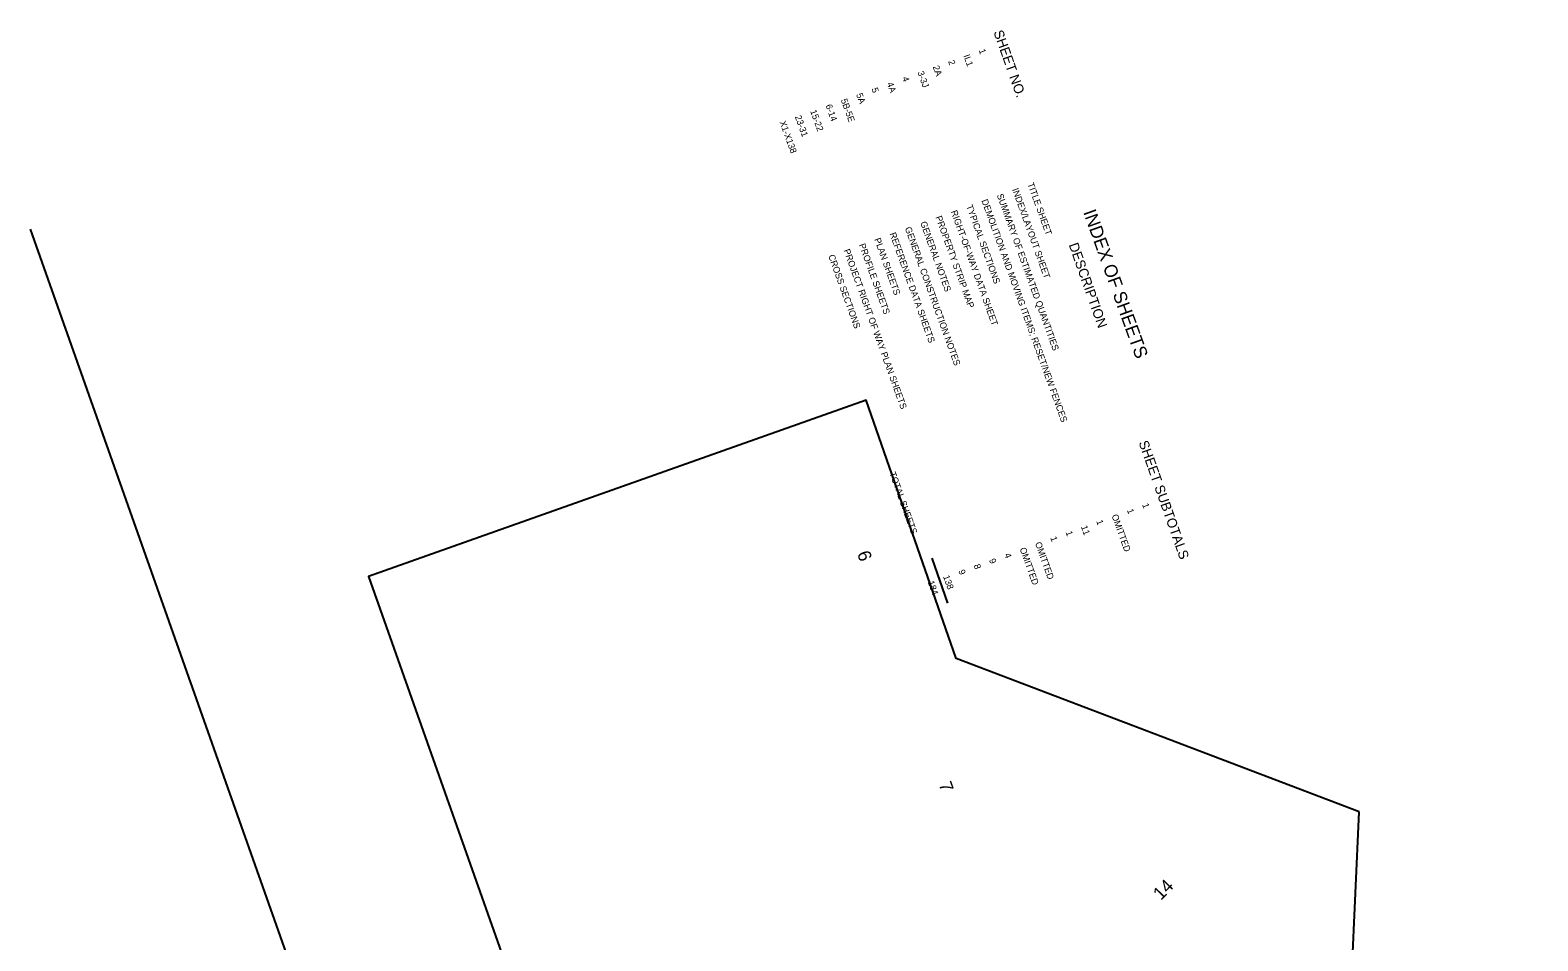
# Model space of a CAD drawing. Extents: x 2000223 to 2009769, y 1132098 to 1143273.
# Drawn here: x 2000223 to 2009479, y 1137686 to 1143273 of the extents above; entities that cross this region are included whole.
import ezdxf

# ---------------------------------------------------------------- set-up
doc = ezdxf.new("R2010")
doc.units = 0
doc.layers.add('RD_SHT_ShtClip', color=7, linetype='Continuous')
doc.layers.add('RD_SHT_TX', color=7, linetype='Continuous')

msp = doc.modelspace()

# ---------------------------------------------------------------- linework, layer by layer
at = {"layer": 'RD_SHT_ShtClip'}
msp.add_lwpolyline([(2008381.9, 1138477.9), (2005909, 1139418.3), (2005354.6, 1141003.5), (2002299.7, 1139921.3), (2004881.5, 1132623.3), (2009479.3, 1134249.9), (2008336.7, 1137479.8)], close=True, dxfattribs=at)
at = {"layer": 'RD_SHT_TX'}
for p, q in [((2000223, 1142053.2), (2003744.9, 1132097.8)), ((2005758, 1140032.7), (2005855.7, 1139756.7))]:
    msp.add_line(p, q, dxfattribs=at)

# ---------------------------------------------------------------- texts
for s, height, rotation, p in [('SHEET NO.', 60, 289.48201, (2006136.7, 1143261.6)), ('1', 40, 289.84288, (2006046, 1143150.3)), ('2', 40, 289.84288, (2005857.9, 1143082.4)), ('IL1', 40, 289.84288, (2005951.9, 1143116.3)), ('4', 40, 289.84288, (2005575.7, 1142980.5)), ('3-3J', 40, 289.84288, (2005669.7, 1143014.5)), ('2A', 40, 289.84288, (2005763.8, 1143048.4)), ('5A', 40, 289.84288, (2005293.5, 1142878.7)), ('5', 40, 289.84288, (2005387.5, 1142912.6)), ('4A', 40, 289.84288, (2005481.6, 1142946.6)), ('15-22', 40, 289.84288, (2005011.3, 1142776.9)), ('6-14', 40, 289.84288, (2005105.4, 1142810.8)), ('5B-5E', 40, 289.84288, (2005199.4, 1142844.8)), ('X1-X138', 40, 289.84288, (2004823.2, 1142709)), ('23-31', 40, 289.84288, (2004917.2, 1142742.9)), ('TITLE SHEET', 40, 289.84288, (2006345.1, 1142329.7)), ('DEMOLITION AND MOVING ITEMS; RESET/NEW FENCES', 40, 289.84288, (2006062.9, 1142227.8)), ('SUMMARY OF ESTIMATED QUANTITIES', 40, 289.84288, (2006157, 1142261.8)), ('INDEX/LAYOUT SHEET', 40, 289.84288, (2006251, 1142295.7)), ('PROPERTY STRIP MAP', 40, 289.84288, (2005780.7, 1142126)), ('RIGHT-OF-WAY DATA SHEET', 40, 289.84288, (2005874.8, 1142160)), ('TYPICAL SECTIONS', 40, 289.84288, (2005968.8, 1142193.9)), ('INDEX OF SHEETS', 80, 289.84288, (2006686.8, 1142156.7)), ('GENERAL CONSTRUCTION NOTES', 40, 289.84288, (2005592.6, 1142058.1)), ('GENERAL NOTES', 40, 289.84288, (2005686.6, 1142092.1)), ('PROFILE SHEETS', 40, 289.84288, (2005310.4, 1141956.3)), ('PLAN SHEETS', 40, 289.84288, (2005404.5, 1141990.2)), ('REFERENCE DATA SHEETS', 40, 289.84288, (2005498.5, 1142024.2)), ('DESCRIPTION', 60, 289.48201, (2006598.4, 1141956.5)), ('CROSS SECTIONS', 40, 289.84288, (2005122.3, 1141888.4)), ('PROJECT RIGHT OF WAY PLAN SHEETS', 40, 289.84288, (2005216.3, 1141922.4)), ('SHEET SUBTOTALS', 60, 289.48201, (2007027.6, 1140743.3)), ('                                                                                             TOTAL SHEETS', 40, 289.84288, (2005028.2, 1141854.5)), ('OMITTED', 40, 289.84288, (2006861.6, 1140294.6)), ('1', 40, 289.84288, (2006955.7, 1140328.6)), ('1', 40, 289.84288, (2007049.7, 1140362.5)), ('1', 40, 289.84288, (2006579.4, 1140192.8)), ('11', 40, 289.84288, (2006673.5, 1140226.7)), ('1', 40, 289.84288, (2006767.6, 1140260.7)), ('OMITTED', 40, 289.84288, (2006297.2, 1140091)), ('OMITTED', 40, 289.84288, (2006391.3, 1140124.9)), ('1', 40, 289.84288, (2006485.4, 1140158.9)), ('6', 80, 289.48201, (2005298.8, 1140062.8)), ('9', 40, 289.84288, (2006109.1, 1140023.1)), ('4', 40, 289.84288, (2006203.2, 1140057)), ('138', 40, 289.84288, (2005826.9, 1139921.2)), ('9', 40, 289.84288, (2005921, 1139955.2)), ('8', 40, 289.84288, (2006015.1, 1139989.1)), ('184', 40, 289.84288, (2005732.9, 1139887.3)), ('7', 80, 289.48201, (2005799.8, 1138646.5)), ('14', 80, 45.6253, (2007165.7, 1137930.4))]:
    msp.add_text(s, height=height, rotation=rotation, dxfattribs=at).set_placement(p)

doc.saveas('drawing.dxf')
